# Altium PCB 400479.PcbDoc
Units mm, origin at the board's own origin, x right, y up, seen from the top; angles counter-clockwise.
Board outline 46.04 x 15.24 mm, 4 copper layers (Top Layer, Mid-Layer 1, Mid-Layer 2, Bottom Layer), stack 2.007 mm thick; 83 components, 46 nets, 247 pads, 135 vias.
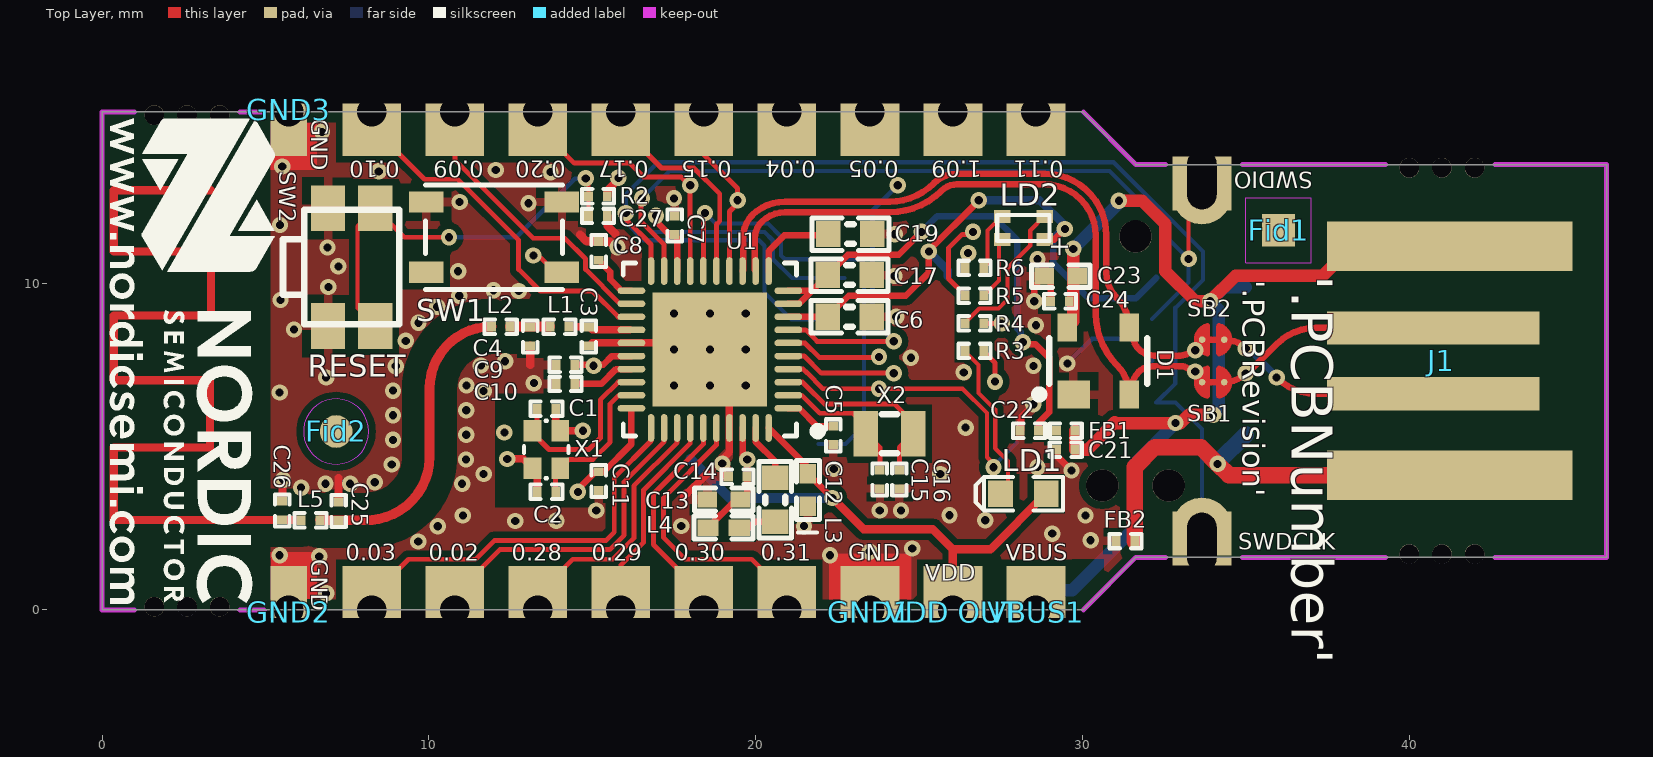
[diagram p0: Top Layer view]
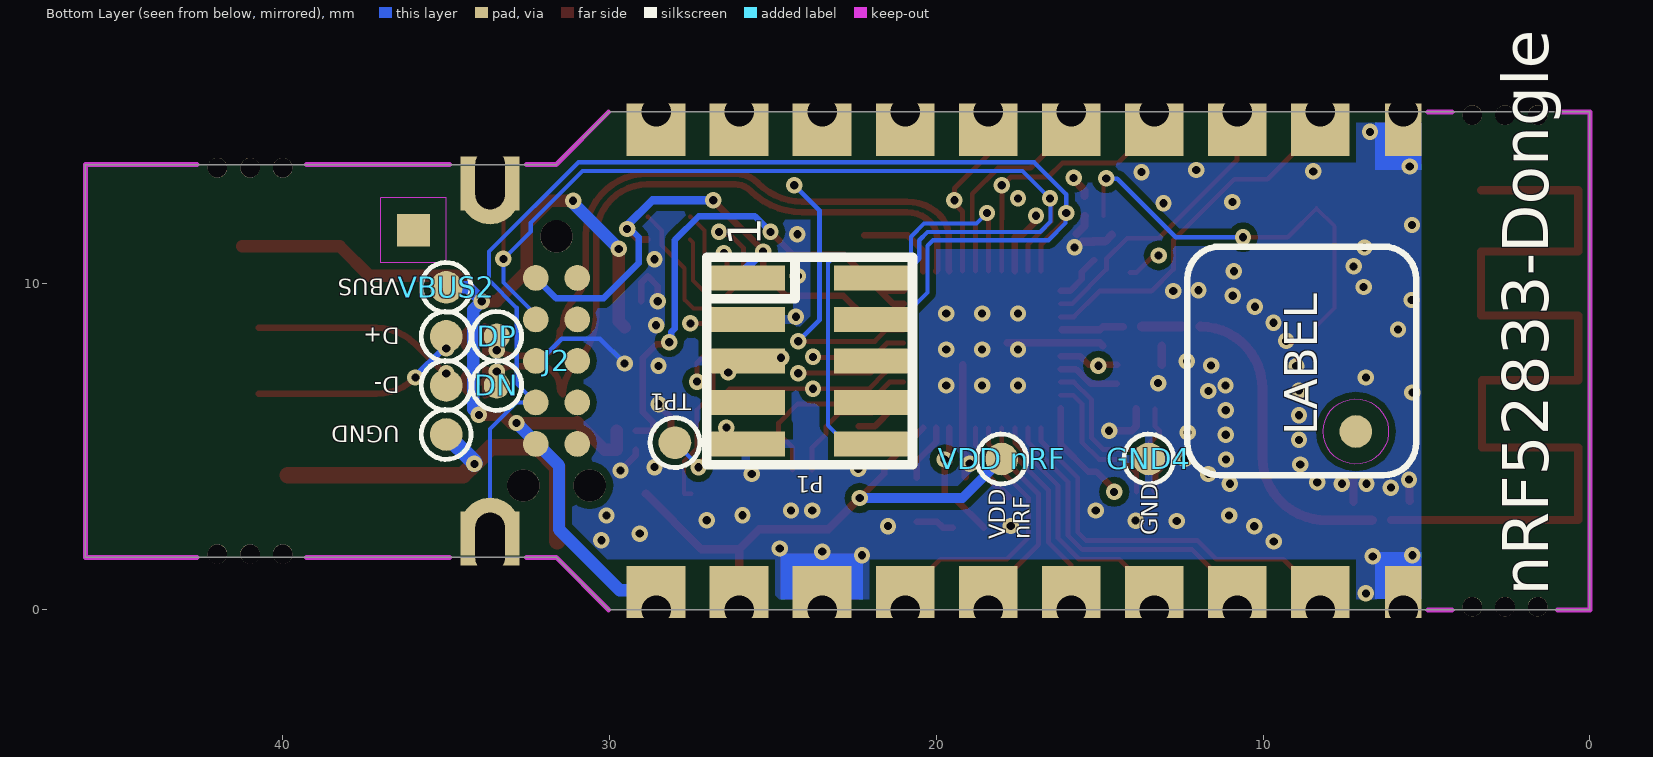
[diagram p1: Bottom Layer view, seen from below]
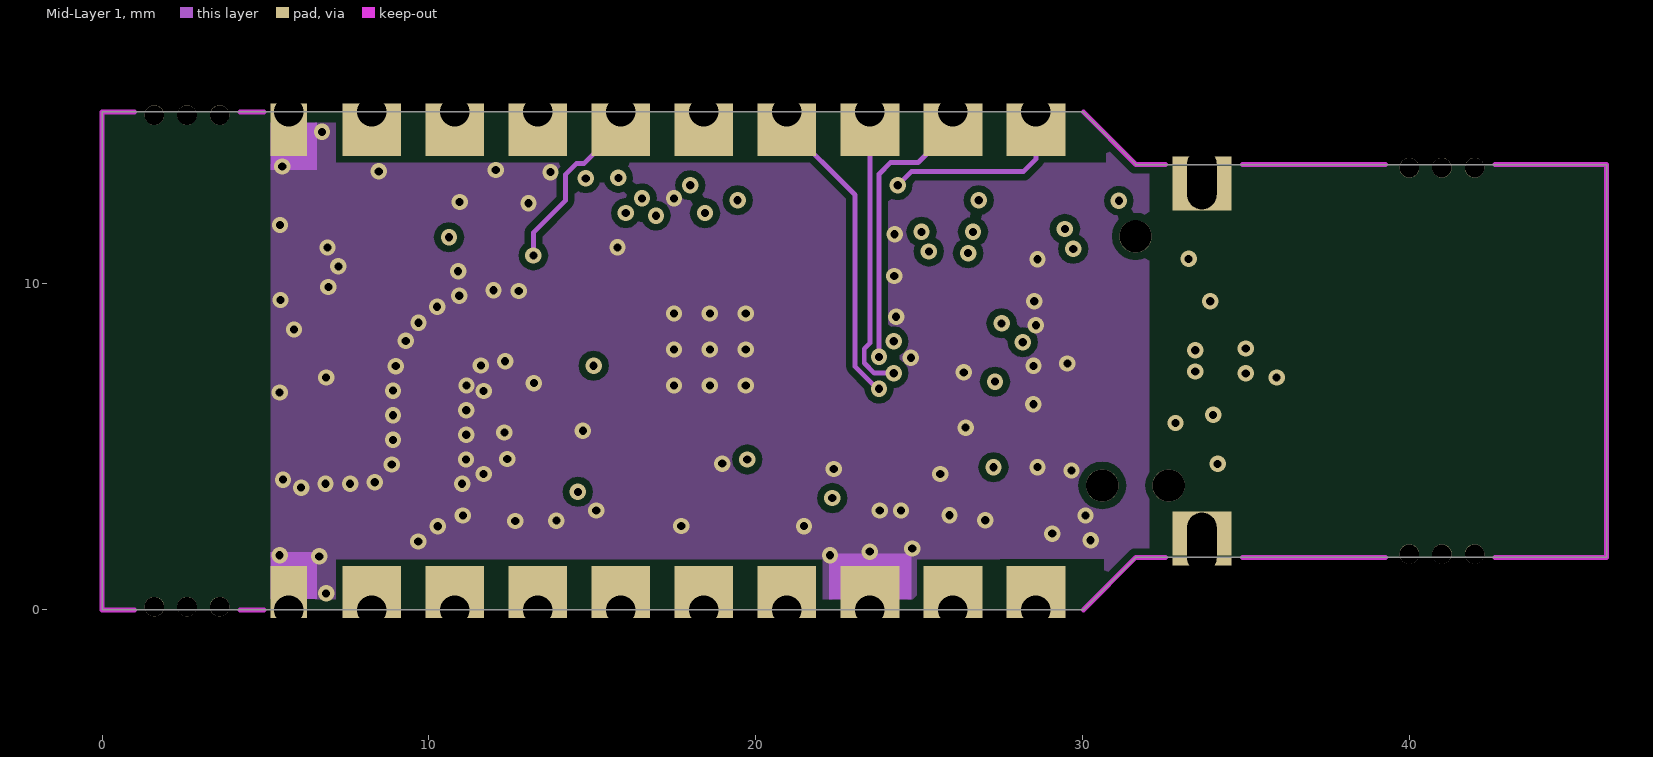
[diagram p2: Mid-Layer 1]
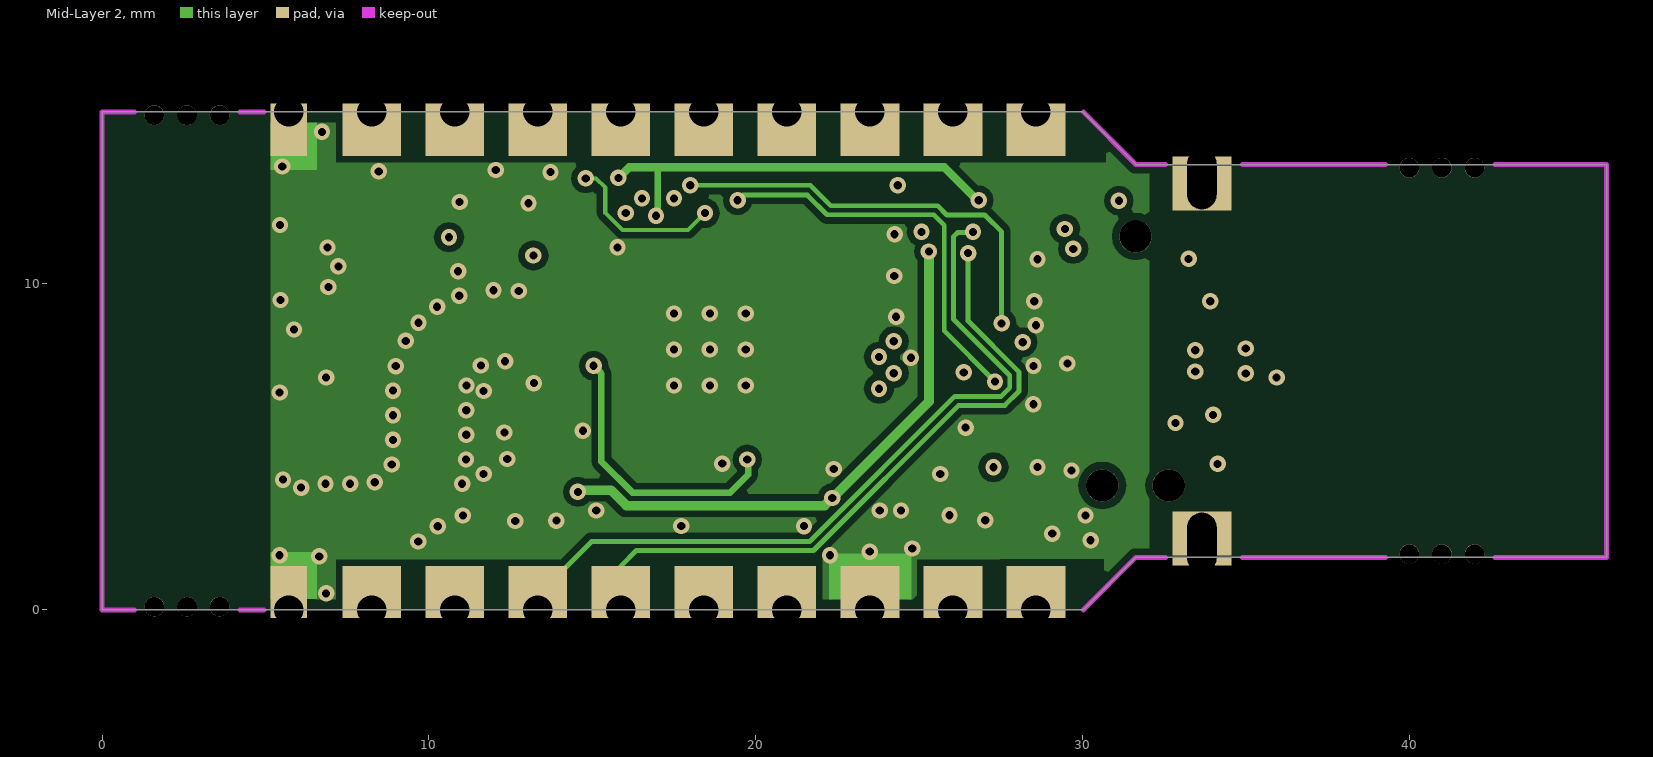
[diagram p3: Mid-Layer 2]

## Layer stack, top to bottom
Top Solder: solder mask 0.018, Solder Resist, Dk 3.5
Top Layer: signal copper 0.018
Dielectric1: prepreg 0.1, FR-4, Dk 4.1
Mid-Layer 1: signal copper 0.0356
Dielectric2: core 1.7, FR-4, Dk 4.5
Mid-Layer 2: signal copper 0.0356
Dielectric3: prepreg 0.1, FR-4, Dk 4.1
Bottom Layer: signal copper 0.018
Bottom Solder: solder mask 0.018, Solder Resist, Dk 3.5

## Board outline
0,0 0,15.24 30.027,15.24 31.637,13.63 46.039,13.63 46.039,1.61 31.637,1.61 30.027,0

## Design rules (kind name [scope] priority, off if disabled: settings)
Clearance ANT_Clerance [(InNet('ANT') or InNet('RF') or InNet('NetC4_2')) and (IsTrack or IsArc or IsVia) vs (InNamedPolygon('Top_Layer-GND')) or (InNamedPolygon('Bottom_Layer-GND')) or (InNamedPolygon('Mid_Layer_1-GND')) or (InNamedPolygon('Mid_Layer_2-GND'))] p1: gap=0.7 ignorepadtopadclearanceinfootprint=FALSE
Clearance NPTH [Not PadIsPlated And HoleSize > 0] p2: gap=0.229 ignorepadtopadclearanceinfootprint=FALSE except(0: Arc-Hole Track-Hole SMDPad-Hole THPad-Hole Via-Hole Fill-Hole Poly-Hole Region-Hole Text-Hole)
Clearance Polygon_Clearance [(InNamedPolygon('Top_Layer-GND')) or (InNamedPolygon('Bottom_Layer-GND')) or (InNamedPolygon('Mid_Layer_1-GND')) or (InNamedPolygon('Mid_Layer_2-GND'))] p3: gap=0.203 ignorepadtopadclearanceinfootprint=FALSE
Clearance SB_Clearance [HasFootprint('Solderbridge')] p4: gap=0.127 ignorepadtopadclearanceinfootprint=FALSE except(0: Arc-Hole Track-Hole SMDPad-Hole THPad-Hole Via-Hole Fill-Hole Poly-Hole Region-Hole Text-Hole)
Clearance [All] p5: gap=0.127 ignorepadtopadclearanceinfootprint=FALSE
ComponentClearance [All] p1 off: gap=0.254 collisioncheckmode=3 verticalgap=0.254 showdistances=FALSE
DiffPairsRouting [All] p1: maxlimit=2.54 minlimit=0.127 mostfreqgap=0.127 toplayer_maxgap=0.127 toplayer_minwidth=0.2 toplayer_maxwidth=0.2 toplayer_prefwidth=0.2 midlayer1_minwidth=0.381 midlayer1_maxwidth=0.381 midlayer1_prefwidth=0.381 midlayer2_minwidth=0.381 midlayer2_maxwidth=0.381 midlayer2_prefwidth=0.381 bottomlayer_maxgap=0.127 bottomlayer_minwidth=0.2 bottomlayer_maxwidth=0.2 bottomlayer_prefwidth=0.2 maxuncoupledlength=12.7
FabricationTestPointUsage TestPointUsage [All] p1: valid=0 allowmultiple=FALSE
FabricationTestpoint Testpoint [All] p1: side=3 testpointundercomponent=TRUE minsize=1.016 maxsize=2.54 preferedsize=1.524 minholesize=0 maxholesize=1.016 preferedholesize=0.813 testpointgrid=0.025 allowsidetop=TRUE allowsidebottom=TRUE usegrid=TRUE gridtolerance=0
Height [All] p1 off: minheight=0 maxheight=25.4 prefheight=12.7
HoleSize [All] p1: absolutevalues=TRUE maxlimit=2.54 minlimit=0.1 maxpercent=80.000 minpercent=20.000
MinimumAnnularRing [All] p1 off: minimumring=0.152
PolygonConnect PolygonConnect_1 [isVia and innet(gnd)] p1: connectstyle=Direct reliefconductorwidth=0.254 reliefentries=4 polygonreliefangle="90 Angle" airgapwidth=0.254
PolygonConnect [All] p2: connectstyle=Relief reliefconductorwidth=0.254 reliefentries=4 polygonreliefangle="90 Angle" airgapwidth=0.254
RoutingVias [All] p1: holewidth=0.25 width=0.5 viastyle="Through Hole" minholewidth=0.1 minwidth=0.3 maxholewidth=0.305 maxwidth=0.61
SilkToSolderMaskClearance SilkscreenOverComponentPads [IsPad] p1: minsilkscreentomaskgap=0.254 clearancetoexposedcopper=TRUE
SolderMaskExpansion [All] p1: expansion=0.076 istentingtop=FALSE
Width [All] p1: maxlimit=2.54 minlimit=0.127 preferedwidth=0.152 minimp=50.000000 maximp=50.000000 favimp=50.000000
23 further rules are at their usual default settings.

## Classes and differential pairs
differential pair D: +D_P -D_N

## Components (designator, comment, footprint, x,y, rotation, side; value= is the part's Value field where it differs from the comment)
0.02 "CH" Castellated_Hole_0.9mm 10.795,0 r0 top locked
0.03 "CH" Castellated_Hole_0.9mm 8.255,0 r0 top locked
0.04 "CH" Castellated_Hole_0.9mm 20.955,15.24 r180 top locked
0.05 "CH" Castellated_Hole_0.9mm 23.495,15.24 r180 top locked
0.09 "CH" Castellated_Hole_0.9mm 10.795,15.24 r180 top locked
0.10 "CH" Castellated_Hole_0.9mm 8.255,15.24 r180 top locked
0.11 "CH" Castellated_Hole_0.9mm 28.575,15.24 r180 top locked
0.15 "CH" Castellated_Hole_0.9mm 18.415,15.24 r180 top locked
0.17 "CH" Castellated_Hole_0.9mm 15.875,15.24 r180 top locked
0.20 "CH" Castellated_Hole_0.9mm 13.335,15.24 r180 top locked
0.28 "CH" Castellated_Hole_0.9mm 13.335,0 r0 top locked
0.29 "CH" Castellated_Hole_0.9mm 15.875,0 r0 top locked
0.30 "CH" Castellated_Hole_0.9mm 18.415,0 r0 top locked
0.31 "CH" Castellated_Hole_0.9mm 20.955,0 r0 top locked
1.09 "CH" Castellated_Hole_0.9mm 26.035,15.24 r180 top locked
C1 "12pF" CAPC0603X03L_C 13.596,6.154 r0 top
C2 "12pF" CAPC0603X03L_C 13.596,3.614 r180 top
C3 "1.0pF" CAPC0603X03L_C 14.9,8.37 r90 top
C4 "1.2pF" CAPC0603X03L_C 13.1,8.37 r90 top
C5 "100nF" CAPC0603X03L_C 22.375,5.345 r270 top
C6 "4.7µF" CAPC1608X06L 22.875,8.97 r0 top
C7 "100nF" CAPC0603X03L_C 17.525,11.77 r90 top
C8 "820pF" CAPC0603X03L_C 15.2,10.987 r90 top
C9 "N.C." CAPC0603X03L_C_NC 14.18,7.5 r0 top
C10 "100pF" CAPC0603X03L_C 14.18,6.916 r180 top
C11 "100nF" CAPC0603X03L_C 15.2,3.945 r270 top
C12 "1.0µF" CAPC1005X04L 21.6,3.67 r270 top
C13 "1.0µF" CAPC1005X04L 19.025,3.38 r0 top
C14 "47nF" CAPC0603X03L_C 19.451,4.08 r180 top
C15 "12pF" CAPC0603X03L_C 23.8,3.995 r270 top
C16 "12pF" CAPC0603X03L_C 24.4,3.995 r270 top
C17 "4.7µF" CAPC1608X06L 22.875,10.245 r0 top
C19 "4.7µF" CAPC1608X06L 22.9,11.5 r0 top
C21 "10nF" CAPC0603X03L_C 29.489,4.902 r0 top locked
C22 "100nF" CAPC0603X03L_C 28.372,5.486 r0 top locked
C23 "4.7µF" CAPC1005X04L 29.337,10.211 r0 top locked
C24 "100nF" CAPC0603X03L_C 29.312,9.449 r0 top locked
C25 "N.C." CAPC0603X03L_C_NC 7.239,3.023 r90 top locked
C26 "1.7pF" CAPC0603X03L_C 5.512,3.048 r270 top locked
C27 "100nF" CAPC0603X03L_C 15.173,12.057 r180 top
D1 "PRTR5V0U2X" SOT190P230X110-4L 30.48,7.62 r90 top locked
D+ "Ø1.0mm,SMD" TP_SMD_D1.0mm#1 35,8.37 r180 bottom locked
D- "Ø1.0mm,SMD" TP_SMD_D1.0mm#1 35,6.87 r180 bottom locked
DN "Ø1.0mm,SMD" TP_SMD_D1.0mm#2 33.45,6.87 r270 bottom locked
DP "Ø1.0mm,SMD" TP_SMD_D1.0mm#2 33.45,8.37 r270 bottom locked
FB1 "120R/0.85A" INDC0603X03L_C 29.489,5.486 r180 top locked
FB2 "120R/0.85A" INDC0603X03L_C 31.318,2.108 r180 top locked
Fid1 "Fiducial mark" Fiducial_Square 36,11.62 r0 top locked value=N.A.
Fid2 "Fiducial mark" Fiducial 7.163,5.461 r0 top locked value=N.A.
GND1 "GND" Castellated_Hole_0.9mm 23.495,0 r0 top locked
GND2 "GND" Castellated_Hole_0.9mm_S 5.715,0 r0 top locked
GND3 "GND" Castellated_Hole_0.9mm_S 5.715,15.24 r180 top locked
GND4 "GND" TP_SMD_D1.0mm#1 13.5,4.62 r180 bottom locked
J1 "USB-A" USB-A-PCB 41.039,7.63 r180 top locked
J2 "TC2050-IDC" TC2050-IDC-NLFP 31.623,7.62 r270 bottom locked
L1 "4.7nH" INDC0603X03L_C 14,8.67 r180 top
L2 "2.2nH" INDC0603X03L_C 12.2,8.67 r180 top
L3 "10µH" INDC1608X06L 20.6,3.37 r90 top
L4 "15nH" INDC1005X04L 19.021,2.52 r0 top
L5 "2.7nH" INDC0603X03L_C 6.375,2.743 r180 top locked
LD1 "L0603G" LED_0603_G 28.194,3.556 r0 top locked
LD2 "LED RGB" LED_RGB_0603 28.194,11.684 r90 top locked
P1 "Pin Header 2x5, 1.27mm" HDR_2x5-SMD-1.27mm-NC 23.876,7.62 r270 bottom locked
R2 "10k" RESC0603X03L_C 15.175,12.657 r0 top
R3 "220R" RESC0603X03L_C 26.695,7.925 r0 top locked
R4 "1k2" RESC0603X03L_C 26.695,8.771 r0 top locked
R5 "2k2" RESC0603X03L_C 26.695,9.618 r0 top locked
R6 "390R" RESC0603X03L_C 26.695,10.465 r0 top locked
SB1 "Solderbridge" Solderbridge_Shorted 34,6.97 r0 top locked net-tie
SB2 "Solderbridge" Solderbridge_Shorted 34,8.27 r0 top locked net-tie
SW1 "PB SW" C&K_PTS810 11.995,11.406 r180 top
SW2 "PTS840 GK SMTR LFS" EVQP7A_J_B_K 7.638,10.49 r270 top
SWDCLK "CH" Castellated_Hole_0.9mm_D 33.655,2.06 r0 top locked
SWDIO "CH" Castellated_Hole_0.9mm_D 33.655,13.18 r180 top locked
TP1 "Ø1.0mm,SMD" TP_SMD_D1.0mm#1 28,5.12 r180 bottom locked
U1 "nRF52833-QDAA" QFN40P500X500X50_HS-41N 18.6,7.97 r180 top locked
UGND "Ø1.0mm,SMD" TP_SMD_D1.0mm#1 35,5.37 r180 bottom locked
VBUS1 "VBUS" Castellated_Hole_0.9mm 28.575,0 r0 top locked
VBUS2 "VBUS" TP_SMD_D1.0mm#1 35,9.87 r180 bottom locked
"VDD nRF" "Ø1.0mm,SMD" TP_SMD_D1.0mm#1 18,4.62 r180 bottom locked
"VDD OUT" "CH" Castellated_Hole_0.9mm 26.035,0 r0 top locked
X1 "32MHz" BT-XTAL_1612 13.596,4.909 r270 top
X2 "32.768kHz" XTAL_2012 24.1,5.395 r0 top

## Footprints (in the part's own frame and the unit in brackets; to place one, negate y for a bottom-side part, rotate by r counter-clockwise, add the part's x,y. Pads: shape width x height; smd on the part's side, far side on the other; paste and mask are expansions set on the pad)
BT-XTAL_1612 [mm] "Crystal 1.6 x 1.2 mm"
  rect 0.65x0.55 smd: 1(-0.575,-0.425) 2(0.575,-0.425) 3(0.575,0.425) 4(-0.575,0.425)
  silkscreen extent -0.88,-0.68 0.88,0.68, body extent -0.83,-0.63 0.83,0.63, height 0.41
C&K_PTS810 [mm] "Microminiature SMT Top Actuated"
  rect 1.05x0.65 smd: 0(2.075,1.075) 1(-2.075,1.075) 2(-2.075,-1.075) 2(2.075,-1.075)
  silkscreen extent -2.1,-1.6 2.1,1.6, body extent -2.29,-1.6 2.29,1.6, height 2.5
CAPC0603X03L_C [mm] "Chip Capacitor, 2-Leads, Body 0.6x0.3mm, IPC High Density"
  rect 0.27x0.3 smd: 1(-0.285,0) 2(0.285,0)
  silkscreen extent -0.49,-0.22 0.49,0.22, body extent -0.3,-0.15 0.31,0.15, height 0.3
CAPC0603X03L_C_NC [mm] "Chip Capacitor, 2-Leads, Body 0.6x0.3mm, IPC High Density"
  rect 0.27x0.3 smd mask+0.05: 1(-0.285,0) 2(0.285,0)
  silkscreen extent -0.49,-0.22 0.49,0.22
CAPC1005X04L [mm] "Chip Capacitor, 2-Leads, Body 1.0x0.5mm, IPC High Density"
  rect 0.6x0.5 smd: 1(-0.5,0) 2(0.5,0)
  silkscreen extent -0.9,-0.35 0.9,0.35, body extent -0.51,-0.25 0.51,0.25, height 0.5
CAPC1608X06L [mm] "Chip Capacitor, 2-Leads, Body 1.6x0.8mm, IPC High Density"
  rect 0.75x0.8 smd: 1(-0.675,0) 2(0.675,0)
  silkscreen extent -1.17,-0.5 1.17,0.5, body extent -0.8,-0.43 0.8,0.43, height 0.8
Castellated_Hole_0.9mm [mm]
  rect 1.8x0.25 hole 0.25 square: 1(0,-0.126)
  rect 1.8x1.35 hole 0.9 copper offset 0,0.675: 1(0,0)
Castellated_Hole_0.9mm_D [mm]
  rect 1.8x0.25 hole 0.25 square: 1(0,-0.576)
  rect 1.8x1.35 hole 0.9 slot 1.83 at 90 deg copper offset 0,0.275: 1(0,0)
  round 1.8 smd paste-5: 1(0,0.48)
  round 1.8 smd far side paste-5: 1(0,0.48)
Castellated_Hole_0.9mm_S [mm]
  rect 1.118x0.25 hole 0.25 square: 1(0,-0.126)
  rect 1.118x1.35 hole 0.9 copper offset 0,0.675: 1(0,0)
EVQP7A_J_B_K [mm] "Subminiature Side Actuated Tact Switch for SMT"
  rect 1.4x1.05 smd: 1(-1.8,0.725) 1(1.8,0.725) 2(-1.8,-0.725) 2(1.8,-0.725)
  silkscreen extent -1.75,-2.1 1.75,1.45, body extent -2.35,-2.1 2.35,1.45, height 1.35
Fiducial [mm] "Fiducial Mark"
  round 1 smd paste-0.6 mask+0.5: 0(0,0)
  round 1 smd far side paste+0 mask+0.5: 0(0,0)
  Top Layer keep-out circle w0.01: c0,0 r1
  Bottom Layer keep-out circle w0.01: c0,0 r1
Fiducial_Square [mm] "Fiducial Mark"
  rect 1x1 smd paste-10 mask+0.5: 0(0,0)
  rect 1x1 smd far side paste-10 mask+0.5: 0(0,0)
  Top Layer keep-out lines w0.01: -1,-1 -1,1 1,1 1,-1 -1,-1
  Bottom Layer keep-out lines w0.01: -1,-1 1,-1 1,1 -1,1 -1,-1
HDR_2x5-SMD-1.27mm-NC [mm] "SMT MICRO HEADER, (1,27) .050\""
  rect 0.76x2.4 smd: 1(-2.54,-1.95) 2(-2.54,1.95) 3(-1.27,-1.95) 4(-1.27,1.95) 5(0,-1.95) 6(0,1.95) 7(1.27,-1.95) 8(1.27,1.95) 9(2.54,-1.95) 10(2.54,1.95)
  silkscreen extent -3.18,-3.15 3.18,3.15
INDC0603X03L_C [mm] "Chip Inductor, 2-Leads, Body 0.6x0.3mm, IPC High Density"
  rect 0.27x0.3 smd: 1(-0.285,0) 2(0.285,0)
  silkscreen extent -0.49,-0.22 0.49,0.22, body extent -0.31,-0.16 0.31,0.16, height 0.26
INDC1005X04L [mm] "Chip Inductor, 2-Leads, Body 1.0x0.5mm, IPC High Density"
  rect 0.65x0.5 smd: 1(-0.475,0) 2(0.475,0)
  silkscreen extent -0.9,-0.35 0.9,0.35, body extent -0.5,-0.3 0.5,0.3, height 0.5
INDC1608X06L [mm] "Chip Inductor, 2-Leads, Body 1.6x0.8mm, IPC High Density"
  rect 0.75x0.8 smd: 1(-0.675,0) 2(0.675,0)
  silkscreen extent -1.17,-0.5 1.17,0.5, body extent -0.8,-0.48 0.8,0.48, height 0.8
LED_0603_G [mil] "SMD Super Bright LED, GREEN"
  rect 30x32 smd: 1(-27.5,0) 2(27.5,0)
  silkscreen extent -58,-20 48,20, body extent -32,-16 32,16, height 24
LED_RGB_0603 [mm]
  rect 0.4x0.5 smd paste+0: 1(0.35,-0.65) 2(-0.35,0.65) 3(0.35,0.65) 4(-0.35,-0.65)
  silkscreen extent -0.4,-0.8 0.4,0.8, body extent -0.4,-0.8 0.4,0.8, height 0.5
QFN40P500X500X50_HS-41N [mm] "QFN, 40-Leads, Body 5.00x5.00mm, Pitch 0.40mm, Thermal Pad 3.60x3.60mm, IPC Medium Density"
  oval 0.85x0.2 smd: 1(-2.4,1.8) 2(-2.4,1.4) 3(-2.4,1) 4(-2.4,0.6) 5(-2.4,0.2) 6(-2.4,-0.2) 7(-2.4,-0.6) 8(-2.4,-1) 9(-2.4,-1.4) 10(-2.4,-1.8) 21(2.4,-1.8) 22(2.4,-1.4) 23(2.4,-1) 24(2.4,-0.6) 25(2.4,-0.2) 26(2.4,0.2) 27(2.4,0.6) 28(2.4,1) 29(2.4,1.4) 30(2.4,1.8)
  oval 0.2x0.85 smd: 11(-1.8,-2.4) 12(-1.4,-2.4) 13(-1,-2.4) 14(-0.6,-2.4) 15(-0.2,-2.4) 16(0.2,-2.4) 17(0.6,-2.4) 18(1,-2.4) 19(1.4,-2.4) 20(1.8,-2.4) 31(1.8,2.4) 32(1.4,2.4) 33(1,2.4) 34(0.6,2.4) 35(0.2,2.4) 36(-0.2,2.4) 37(-0.6,2.4) 38(-1,2.4) 39(-1.4,2.4) 40(-1.8,2.4)
  rect 3.5x3.5 smd: 41(0,0)
  silkscreen extent -3.43,-2.65 2.65,2.65, body extent -2.5,-2.5 2.5,2.5, height 0.5
RESC0603X03L_C [mm] "Chip Resistor, 2-Leads, Body 0.6x0.3mm, IPC High Density"
  rect 0.27x0.3 smd: 1(-0.285,0) 2(0.285,0)
  silkscreen extent -0.49,-0.22 0.49,0.22, body extent -0.3,-0.15 0.3,0.15, height 0.23
Solderbridge_Shorted [mm]
  round 0.2 smd paste-10: 1(-0.338,0) 2(0.338,0)
  Top Layer region: 0.102,0.432 0.178,0.505 0.296,0.467 0.361,0.424 0.434,0.351 0.488,0.292 0.546,0.193 0.574,0.099 0.569,-0.122 0.544,-0.193 0.46,-0.33 0.376,-0.411 0.284,-0.469 0.183,-0.5 0.132,-0.483 0.102,-0.43
  Top Layer region: -0.102,-0.432 -0.178,-0.505 -0.296,-0.467 -0.361,-0.424 -0.434,-0.351 -0.488,-0.292 -0.546,-0.193 -0.574,-0.099 -0.569,0.122 -0.544,0.193 -0.46,0.33 -0.376,0.411 -0.284,0.469 -0.183,0.5 -0.132,0.483 -0.102,0.43
  Top Layer lines w0.152: -0.178,-0.431 cw(c-0.068,0) -0.178,0.431 ; 0.178,-0.431 ccw(c0.068,0) 0.178,0.431
  Top Layer lines w0.203: -0.338,0 0.338,0
SOT190P230X110-4L [mm] "SOT143, 4-Leads, Body 3.0x2.5mm (max), Pitch 1.90mm, IPC High Density"
  rect 0.85x1 smd: 1(-1.025,0.75)
  rect 0.85x0.6 smd: 2(-1.025,-0.95) 3(1.025,-0.95) 4(1.025,0.95)
  silkscreen extent -1.15,-1.5 0.7,1.92, body extent -1.21,-1.46 1.21,1.46, height 1
TC2050-IDC-NLFP [mil]
  round 39 hole 39 unplated mask+3: 0(-150,0) 0(150,-40) 0(150,40)
  round 31 smd paste-196.85: 1(-100,-25) 2(-50,-25) 3(0,-25) 4(50,-25) 5(100,-25) 6(100,25) 7(50,25) 8(0,25) 9(-50,25) 10(-100,25)
  Top Layer pour cut-out: -100,25 -100,-25 100,-25 100,25
TP_SMD_D1.0mm#1 [mm] "Test point - pad 1.0mm"
  round 1 smd paste-5: 1(0,0)
  silkscreen extent -0.76,-0.76 0.76,0.76
TP_SMD_D1.0mm#2 [mm] "Test point - pad 1.0mm"
  round 0.8 smd paste-5: 1(0,0)
  silkscreen extent -0.76,-0.76 0.76,0.76
USB-A-PCB [mil]
  rect 296x60 smd paste-196.85: 1(-7.87,-137.8) 4(-7.87,138)
  rect 256x40 smd paste-196.85: 2(12,-39.37) 3(12,40)
XTAL_2012 [mm] "XTAL SMD 2.0 x 1.2 mm"
  rect 0.75x1.4 smd: 1(-0.725,0) 2(0.725,0)
  silkscreen extent -0.24,-0.6 0.24,0.6, body extent -1,-0.61 1,0.61, height 0.6

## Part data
0.02 0.03 0.04 0.05 0.09 0.10 0.11 0.15 0.17 0.20 0.28 0.29 0.30 0.31 1.09 GND1 VBUS1 "VDD OUT": library part "Castellated Hole 0.9mm", "Castellated Hole 0.9mm", Manufacturer=N.A.
C1 C2 C15 C16: library part C0201-12p, "Capacitor, NP0, ±2%", Manufacturer=N.A., Part number IPS=00000007848
C3: library part C0201-1.0p, "Capacitor, NP0, ±0.05pF, 50V", Manufacturer=N.A., Part number IPS=00000001247
C4: library part C0201-1.2p, "Capacitor, C0G, ±0.1pF, 50V", Manufacturer=N.A., Part number IPS=00000003190
C5 C7 C11 C22 C24 C27: library part C0201-100n, "Capacitor, X5R, ±10%", Manufacturer=N.A., Part number IPS="00000001248, 00000002505"
C6 C19: library part C0603-4µ7-6.3V-X7R, "Capacitor, X7R, ±10%, 6.3V", Manufacturer="Samsung Electro-Mechanics America", Manufacturer Part Number=CL10B475KQ8NQNC, Part number IPS=00000002541, Part number Norautron=N.A., Supplier Part Number 1=1276-2087-1-ND
C8: library part C0201-820p, "Capacitor, X7R, ±10%", Manufacturer=N.A., Part number IPS=00000001249
C9 C25: library part C0201-N.C., "Not mounted", Manufacturer=N.A.
C10: library part C0201-100p, "Capacitor, NP0, ±2%, 25V", Manufacturer=Murata, Manufacturer Part Number=GRM0335C1E101GA01, Part number IPS=00000007853, Part number Norautron=N.A.
C12 C13: library part C0402-1µ0, "Capacitor, X5R, ±5%, 6.3V", Manufacturer=N.A., Part number IPS="00000007786, 00000003457", Supplier Part Number 1=1276-1444-1-ND
C14: library part C0201-47n, "Capacitor, X5R, ±10%", Manufacturer=N.A., Part number IPS=00000001250
C17: library part C0603-4µ7-10V-X7S, "Capacitor, X7S, ±10%, 10V", Manufacturer=N.A., Part number IPS=00000001779, Supplier Part Number 1=445-14258-1-ND
C21: library part C0201-10n, "Capacitor, X7R, ±10%", Manufacturer=N.A., Part number IPS=00000003480
C23: library part C0402-4µ7, "Capacitor, X5R, ±20%", Manufacturer=N.A., Part number IPS="00000001251, 00000007165", Supplier Part Number 1=490-13252-1-ND
C26: library part C0201-1.7p, "Chip Cap 0201", Manufacturer=N.A.
D1: "Ultra low capacitance double rail-to-rail ESD protection diode", Manufacturer="NXP Semiconductors", Part number IPS=00000009951, Part number Norautron=N.A., Supplier Part Number 1=568-4140-1-ND
D+ D- DN DP GND4 TP1 UGND VBUS2 "VDD nRF": library part TP_SMD_Ø1.0MM, "1.0mm circular SMD testpad", Manufacturer="Nordic Semiconductor", Manufacturer Part Number=N.A.
FB1 FB2: library part FB0201-120R@100M-850mA, "Ferrite Bead, 120 Ohm @ 100MHz, 850mA, 150 mOhm Max", Manufacturer="Taiyo Yuden", Manufacturer Part Number=BKP0603HS121-T, Part number IPS=00000001252, Part number Norautron=N.A., Supplier Part Number 1=587-3286-1-ND
Fid1: library part Fid-Mark-Square, "Fiducial Mark", Manufacturer=N.A.
Fid2: library part Fid-Mark, "Fiducial Mark", Manufacturer=N.A.
GND2 GND3: library part "Castellated Hole 0.9mm_S", "Castellated Hole 0.9mm", Manufacturer=N.A.
J1: library part USB-A-PCB, "USB-A PCB footprint", Manufacturer=N.A.
J2: library part TC2050-IDC-NLFP, "CBL PLUG-OF-NAILS 10-PIN", Manufacturer="Tag-Connect LLC", Part number IPS=N.A., Supplier Part Number 1=TC2050-IDC-NL-ND
L1: library part L0201-4n7, "Inductor, 350mA, ±3%", Manufacturer=Murata, Manufacturer Part Number=LQP03TN4N7H02D, Part number IPS=00000001792, Part number Norautron=N.A.
L2: library part L0201-2n2, "Chip Inductor", Manufacturer=N.A.
L3: library part L0603-10µ-TDK, "Inductor, 250mA, ±20%, 1.05ohm. -55°C ~ 125°C", Manufacturer="TDK Corporation", Manufacturer Part Number=MLZ1608M100WTD25, Part number IPS=N.A., Supplier Part Number 1=445-175588-1-ND
L4: library part L0402-15n, "Inductor, 320mA, ±5%", Manufacturer="Taiyo Yuden", Manufacturer Part Number=HK100515NJ-T, Part number IPS=00000001262, Part number Norautron=N.A., Supplier Part Number 1=587-1521-1-ND
L5: library part L0201-2n7, "Chip Inductor", Manufacturer=N.A.
LD1: library part "VS 25C7M5", "LED, Green, 0603, 573nm, Vf=2.0V, 24mcd, - 40 to +85°C", Manufacturer="Victory Electronics", Part number IPS="00000001274, 00000009961", Part number Norautron=N.A.
LD2: library part APHF1608LSEEQBDZGKC, "RGB LED 1.60 mm x 0.80 mm SMD", Manufacturer="Kingbright Company LLC", Part number IPS=00000001254, Part number Norautron=N.A., Supplier Part Number 1=754-2143-1-ND
P1: library part "Pin Header 2x5 SMD, 1.27mm, KS, N.C.", "Pin Header 2x5, 1.27mm (50mil), SMD, Keying Shroud", Manufacturer=W-CON, Manufacturer Part Number=3132-10MS0BK00R1, Part number IPS=N.A.
R2: library part R0201-10k, "Resistor, ±1%, 0.05W", Manufacturer=N.A., Part number IPS=00000001255
R3: library part R0201-220, "Resistor, ±1%, 0.05W", Manufacturer=N.A., Part number IPS=00000000863
R4: library part R0201-1k2, "Resistor, ±1%, 0.05W", Manufacturer=N.A., Part number IPS=00000001256
R5: library part R0201-2k2, "Resistor, ±1%, 0.05W", Manufacturer=N.A., Part number IPS=00000001257
R6: library part R0201-390, "Resistor, ±1%, 0.05W", Manufacturer=N.A., Part number IPS=00000001258
SB1 SB2: library part "Solderbridge Shorted", "Shorted Solderbridge", Manufacturer=N.A.
SW1: library part "PTS810 SJK 250 SMTR LFS", "Tactile Switch, SPNO, SMD, 260gf, 4.2x3.2x2.5mm", Manufacturer=C&K, Part number IPS=00000001259, Part number Norautron=N.A., Supplier Part Number 1=CKN10503TR-ND
SW2: "Microminiature SMT Switch, Side Actuated", Manufacturer=C&K, Part number IPS=00000001260, Part number Norautron=N.A., Supplier Part Number 1=CKN10508CT-ND
SWDCLK SWDIO: library part "Castellated Hole 0.9mm_D", "Castellated Hole 0.9mm", Manufacturer=N.A.
U1: "Multi-protocol Bluetooth Low Energy, IEEE 802.15.4, ANT and 2.4GHz proprietary system-on-chip", Manufacturer="Nordic Semiconductor", Part number IPS=N.A.
X1: library part XTAL_SMD1612_32MHz_8pF_General, "XTAL SMD 1612, 32MHz, Cl=8pF, Total Tol: ±40ppm", Manufacturer=N.A.
X2: library part XTAL_SMD2012_32.768kHz_9pF_General, "XTAL SMD 2012, 32.768kHz, Cl=9pF, Total Tol: ±50ppm", Manufacturer=N.A.

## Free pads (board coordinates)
  round 1.8 smd paste-5: 3(33.655,2.54) 3(33.655,12.7)
  round 1.8 smd far side paste-5: 3(33.655,2.54) 3(33.655,12.7)
  round 0.6 hole 0.6 unplated paste+0 mask+0.102: 4(1.6,0.1) 4(1.6,15.14) 4(2.6,0.1) 4(2.6,15.14) 4(3.6,0.1) 4(3.6,15.14) 4(40,1.71) 4(40,13.53) 4(41,1.71) 4(41,13.53) 4(42,1.71) 4(42,13.53)

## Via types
v1: diameter 0.5, hole 0.25, Top Layer to Bottom Layer, tented both sides, 135 vias

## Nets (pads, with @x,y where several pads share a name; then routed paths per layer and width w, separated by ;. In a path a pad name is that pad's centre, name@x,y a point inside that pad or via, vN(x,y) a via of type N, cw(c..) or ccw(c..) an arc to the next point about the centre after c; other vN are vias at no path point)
ANT: C26.2 L5.2 | length 30.6
  Top Layer w0.254: 3.327,12.846 0.363,12.846 0.363,10.966 3.332,10.966 3.332,9.01 0.363,9.01 0.363,7.029 3.307,7.029 3.307,4.972 0.363,4.972 0.363,2.754 L5.2@6.09,2.754
D_N: D1.2 DN.1 SB1.1 U1.12 | length 21.1
  Top Layer w0.2: 19.975,11.401 19.975,11.376 ; U1.12 cw(c20.06,10.43) 19.975,10.43 19.975,11.376 ; SB1.1 33.3,7.332 ccw(c33,7.032) 33,7.457 32.15,7.457 ccw(c32.15,6.836) 31.53,6.836 cw(c31.189,6.836) D1.2 ccw(c30.163,6.595) 31.059,7.491 cw(c32.632,9.065) 30.407,9.065 30.407,11.456 ccw(c28.839,11.456) 28.839,13.023 26.162,13.023 ccw(c26.162,12.345) 25.682,12.825 cw(c24.096,14.41) 24.096,12.168 20.9,12.168 ccw(c20.9,11.149) 20.18,11.87 ccw(c20.674,11.376) 19.975,11.376
  other v1: 33.45,7.295
D_P: D1.3 DP.1 SB2.1 U1.13 | length 20
  Top Layer w0.2: U1.13 ccw(c19.537,10.433) 19.626,10.433 19.626,11.429 ; 19.626,11.454 19.626,11.429 ; SB2.1 33.3,7.908 cw(c33,8.208) 33,7.783 32.2,7.783 cw(c32.2,8.454) 31.53,8.454 ccw(c31.309,8.454) 31.465,8.61 D1.3 ccw(c30.163,8.645) 31.059,9.541 cw(c31.843,10.325) 30.734,10.325 30.734,11.456 ccw(c28.839,11.456) 28.839,13.35 26.162,13.35 ccw(c26.162,12.345) 25.451,13.056 cw(c24.096,14.41) 24.096,12.495 20.9,12.495 ccw(c20.9,11.074) 19.895,12.079 ccw(c20.546,11.429) 19.626,11.429
  other v1: 33.45,7.945
DEC1: C5.1 U1.1 | length 1.6
  Top Layer w0.2: U1.1 21.333,6.17 21.879,5.624 C5.1@22.375,5.624
DEC3: C10.1 U1.27 | length 1.9
  Top Layer w0.2: C10.1@14.485,6.917 15.279,6.917 15.732,7.37 U1.27
DEC4_6: C9.2 C13.2 C14.1 L4.1 U1.26 U1.38 | length 14
  Top Layer w0.2: C9.2 15.335,7.5 15.605,7.77 U1.26 ; L4.1 19.406,3.38 C13.2 ; U1.38 19.6,4.655 19.678,4.655 v1@19.736,4.597 ; C13.2@19.743,3.423 v1(19.743,4.604)
  Mid-Layer 2 w0.2: v1(15.044,7.472) 15.282,7.234 15.282,4.538 16.23,3.59 19.22,3.59 19.768,4.138 v1@19.768,4.554
GND: C1.2 C2.2 C3.1 C4.1 C5.2 C6.2 C7.2 C8.2 C9.1 C10.2 C11.2 C12.2 C13.1 C14.2 C15.2 C16.2 C17.2 C19.2 C21.1 C22.1 C23.1 C24.1 C25.2 C26.1 C27.1 D1.1 FB2.2 GND1.1 GND2.1 GND3.1 GND4.1 J2.3 P1.3 P1.5 P1.9 SW1.2 SW2.2 U1.25 U1.37 U1.41 X1.2 X1.4 | length 21.4
  Top Layer w0.203: C22.1 28.12,5.52 28.12,5.89 28.5,6.27 v1(28.5,6.295) ; v1(28.524,9.449) 28.524,9.906 28.829,10.211 C23.1 29.027,10.021 C24.1 ; C21.1 29.204,4.73 v1(29.667,4.267)
  Top Layer w0.229: v1(12.4,4.62) 12.885,4.62 X1.2 13.311,4.194 C2.2@13.311,3.665 ; C1.2 13.881,5.624 X1.4 v1(14.714,5.484) ; C3.1@14.909,8.085 14.994,8.17 U1.41@17.825,8.17 ; 17.806,3.461 18.518,4.173 ; v1@18.975,4.32 18.975,4.604 19.2,4.829 U1.41@19.2,7.5 ; v1@18.981,4.503 19.115,4.369 C14.2@19.115,4.08
  Top Layer w0.254: C26.1 5.516,3.333 5.524,3.341 5.524,3.975 v1(5.537,3.988) ; C25.2 7.239,4.039 ; 13.1,7.497 C4.1 ; 14.625,11.485 14.83,11.28 15.192,11.28 C8.2 ; C8.2@15.175,11.272 15.183,11.264 15.539,11.264 15.708,11.095 v1(15.775,11.095) ; C27.1 15.466,12.049 15.466,11.752 15.708,11.509
  Bottom Layer w0.145: v1(29.54,7.544) 30.293,8.297 31.464,8.297 J2.3@32.131,7.63
  other v1: 6.858,0.508 6.647,1.638 5.436,1.674 22.275,1.674 23.492,1.786 24.79,1.88 9.677,2.093 30.251,2.134 29.077,2.335 10.274,2.563 17.725,2.57 21.479,2.566 12.645,2.72 13.903,2.735 27.026,2.743 11.043,2.892 25.933,2.896 30.093,2.892 15.125,3.045 23.8,3.045 24.45,3.045 6.093,3.742 6.837,3.864 7.591,3.864 11.018,3.861 8.344,3.909 11.678,4.162 25.648,4.162 22.39,4.316 28.625,4.37 8.867,4.451 18.981,4.478 11.139,4.606 8.904,5.204 11.146,5.36 12.313,5.432 26.425,5.579 8.904,5.958 11.146,6.114 5.436,6.655 8.904,6.712 11.678,6.702 11.151,6.868 17.5,6.87 18.6,6.87 19.7,6.87 13.215,6.941 6.858,7.112 26.37,7.27 8.989,7.461 28.501,7.47 11.592,7.479 12.334,7.609 24.75,7.72 17.5,7.97 18.6,7.97 19.7,7.97 9.292,8.233 5.875,8.581 28.575,8.712 9.684,8.787 24.3,8.97 17.5,9.07 18.6,9.07 19.7,9.07 10.255,9.28 5.463,9.483 10.93,9.614 12.75,9.761 11.977,9.782 6.925,9.884 24.244,10.22 10.897,10.363 7.233,10.512 28.625,10.731 6.899,11.091 24.252,11.495 5.445,11.78 13.05,12.445 10.944,12.482 17.5,12.595 8.47,13.42 13.725,13.398 12.05,13.462 5.513,13.57 6.731,14.63
LED1: 0.15.1 R3.2 U1.14 | length 18.7
  Top Layer w0.15: 18.415,15.24 18.415,13.93 19.45,12.895 v1(19.45,12.536) 19.45,12.441 19.2,12.191 U1.14 ; R3.2 26.98,7.91 27.325,7.565 v1(27.325,6.988)
  Mid-Layer 2 w0.15: v1(19.45,12.536) 19.609,12.695 21.581,12.695 22.184,12.092 25.452,12.092 25.772,11.772 25.772,8.54 v1(27.325,6.988)
LED2_B: 0.29.1 R6.1 U1.34 | length 27.5
  Top Layer w0.15: 0.29.1@15.875,0 15.875,1.37 16.575,2.07 16.575,3.672 18,5.097 U1.34 ; v1@26.401,10.92 26.406,10.916 26.406,10.469 R6.1
  Mid-Layer 2 w0.15: 0.29.1@15.875,0 15.875,1.343 16.35,1.818 21.772,1.818 26.212,6.259 27.627,6.259 28.054,6.686 28.054,7.289 26.501,8.842 v1(26.501,10.92)
LED2_G: 0.28.1 R5.1 U1.33 | length 34.1
  Top Layer w0.15: 0.28.1@13.335,0 13.335,0.48 14.408,1.553 15.634,1.553 16.275,2.194 16.275,3.796 17.6,5.121 U1.33 ; R5.1 26.41,9.633 25.9,10.144 25.9,11.07 26.325,11.495 26.636,11.495 v1@26.65,11.509
  Mid-Layer 2 w0.15: 0.28.1@13.335,0 13.335,0.45 14.98,2.095 21.657,2.095 26.097,6.536 27.512,6.536 27.777,6.8 27.777,7.175 26.049,8.902 26.049,11.419 26.176,11.546 v1@26.627,11.546
  other v1: 26.651,11.57
LED2_R: 0.20.1 R4.2 U1.17 | length 21.9
  Top Layer w0.15: 13.335,15.24 13.335,14.79 14.453,13.672 16.148,13.672 16.573,13.247 17.723,13.247 17.998,12.972 17.998,11.958 18,11.956 U1.17 ; R4.2@26.981,8.771 v1@27.526,8.771
  Mid-Layer 2 w0.15: v1(17.998,12.995) 21.673,12.995 22.299,12.369 25.567,12.369 25.852,12.084 27.011,12.084 27.526,11.569 v1(27.526,8.77)
NetC3_2: C3.2 L1.1 U1.24 | length 1.9
  Top Layer w0.229: L1.1 14.894,8.67 14.909,8.655 14.994,8.57 U1.24@16.15,8.57
NetC4_2: C4.2 L1.2 L2.1 | length 1.2
  Top Layer w0.3: L2.1 L1.2
NetC8_1: C8.1 U1.21 | length 1.5
  Top Layer w0.2: C8.1@15.175,10.702 15.19,10.702 15.55,10.342 15.55,10.117 15.897,9.77 U1.21
NetC19_1: C19.1 U1.11 | length 2.6
  Top Layer w0.2: U1.11 20.4,10.983 20.882,11.465 ; 20.878,11.468 C19.1@22.21,11.468
NetD+_1: D+.1 J1.3 SB2.2 | length 7
  Top Layer w0.2: SB2.2 34.351,8.27 cw(c34.351,7.352) v1(35,8.001) ; v1(35.941,7.112) ccw(c37.144,8.315) 37.144,6.614 J1.3
  Bottom Layer w0.2: D+.1@35.077,8.001 35.966,7.112 v1@36.043,7.112
NetD-_1: D-.1 J1.2 SB1.2 | length 7
  Top Layer w0.2: SB1.2 34.351,6.97 ccw(c34.351,7.888) v1(35,7.239) ccw(c35,7.355) 35.082,7.273 35.941,8.132 cw(c37.144,6.929) 37.144,8.63 J1.2
NetFB2_1: FB2.1 J1.4 UGND.1 | length 12.4
  Top Layer w0.508: FB2.1 31.603,4.374 32.207,4.978 33.63,4.978 v1(34.138,4.47) 34.483,4.125 J1.4@39.853,4.125
  Bottom Layer w0.508: v1(34.138,4.47) 34.138,4.508 UGND.1
NetL3_1: L3.1 L4.2 | length 1.2
  Top Layer w0.2: L4.2 19.8,2.52 19.975,2.695 20.177,2.695 L3.1
NetL3_2: L3.2 U1.39 | length 1.8
  Top Layer w0.2: U1.39 20,5.15 20.6,4.55 L3.2
NetLD1_1: LD1.1 R3.1 | length 5.1
  Top Layer w0.127: R3.1 26.41,7.91 26.825,7.495 26.825,6.638 27.33,6.132 27.33,4.949 27.72,4.56 27.72,3.556 LD1.1
NetLD2_1: LD2.1 R4.1 | length 4.6
  Top Layer w0.127: R4.1 26.41,8.786 26.844,9.22 27.429,9.22 27.703,9.494 27.703,10.456 28.403,11.157 28.403,11.613 28.825,12.034 LD2.1
NetLD2_2: LD2.2 R5.2 | length 1.9
  Top Layer w0.127: R5.2 27.449,10.086 27.449,11.239 LD2.2
NetLD2_3: LD2.3 R6.2 | length 1.8
  Top Layer w0.127: R6.2 27.1,10.584 27.1,11.609 27.525,12.034 LD2.3
P0.00/XL1: C15.1 U1.2 X2.1 | length 4.3
  Top Layer w0.15: U1.2 21.41,6.57 21.962,6.018 22.975,6.018 ; 22.975,6.02 23.375,5.62 X2.1 23.8,4.97 C15.1
P0.01/XL2: C16.1 U1.3 X2.2 | length 6
  Top Layer w0.15: U1.3 21.433,6.97 21.55,6.853 21.552,6.853 22.1,6.305 24.239,6.305 24.825,5.718 X2.2 24.4,4.97 C16.1
P0.02/AIN0: 0.02.1 U1.32 | length 10.2
  Top Layer w0.15: 0.02.1@10.795,0 10.795,0.465 12.175,1.845 15.534,1.845 15.975,2.286 15.975,3.921 17.2,5.146 U1.32
P0.03/AIN1: 0.03.1 U1.31 | length 12.3
  Top Layer w0.15: 0.03.1@8.255,0 8.255,0.429 9.378,1.552 11.432,1.552 12.002,2.122 15.42,2.122 15.675,2.377 15.675,4.045 16.8,5.17 U1.31
P0.04/AIN2: 0.04.1 TP1.1 U1.4 | length 19.1
  Top Layer w0.127: v1(23.775,6.77) 26.334,6.77 27.076,6.027 27.076,4.674 27.28,4.47 v1(27.28,4.369)
  Top Layer w0.15: U1.4 21.457,7.37 21.557,7.27 21.559,7.27 22.059,6.77 v1(23.775,6.77)
  Mid-Layer 1 w0.15: 20.955,15.24 20.955,14.79 23.046,12.699 23.046,7.443 23.719,6.77 v1(23.775,6.77)
  Bottom Layer w0.127: v1(27.28,4.369) 27.28,4.4 TP1.1
P0.05/AIN3: 0.05.1 U1.5 | length 12.2
  Top Layer w0.15: U1.5 21.483,7.77 22.008,7.245 v1(24.225,7.245)
  Mid-Layer 1 w0.15: 23.495,15.24 23.495,8.165 23.323,7.993 23.323,7.557 23.635,7.245 v1(24.225,7.245)
P0.09: 0.09.1 U1.22 | length 8.9
  Top Layer w0.15: 10.795,15.24 10.795,13.774 13.193,11.376 14.161,11.376 14.797,10.739 14.797,10.421 15.848,9.37 U1.22
P0.10: 0.10.1 U1.23 | length 11.3
  Top Layer w0.15: 8.255,15.24 8.255,14.765 8.28,14.765 9.867,13.178 10.886,13.178 12.748,11.317 12.748,10.422 13.409,9.761 15,9.761 15.791,8.97 U1.23
P0.11: 0.11.1 U1.7 | length 14.7
  Top Layer w0.15: U1.7 21.532,8.57 21.882,8.22 v1(24.226,8.22)
  Mid-Layer 1 w0.15: v1(24.35,12.995) 24.766,13.411 28.191,13.411 28.575,13.795 28.575,15.24
  Bottom Layer w0.15: v1(24.226,8.22) 23.582,8.864 23.582,12.227 v1(24.35,12.995)
P0.30/AIN6: 0.30.1 U1.35 | length 6.8
  Top Layer w0.15: U1.35 18.4,5.073 16.875,3.548 16.875,1.995 18.415,0.455 0.30.1@18.415,0
P0.31/AIN7: 0.31.1 U1.36 | length 9
  Top Layer w0.15: U1.36 18.8,5.049 17.175,3.424 17.175,2.22 17.842,1.553 19.878,1.553 20.955,0.476 0.31.1@20.955,0
P1.09: 1.09.1 U1.6 | length 11.9
  Top Layer w0.15: U1.6 21.508,8.17 21.958,7.72 23.75,7.72 v1(23.775,7.745)
  Mid-Layer 1 w0.15: v1@23.774,7.745 23.774,13.337 24.125,13.688 24.968,13.688 26.035,14.755 26.035,15.24
RESET: C27.2 P1.10 R2.1 SW2.1 U1.16 | length 32
  Top Layer w0.127: SW2.1@8.363,8.69 7.816,9.237 7.816,11.743 8.363,12.29 9.249,11.405 v1(10.617,11.405) ; v1(14.801,13.207) 14.801,13.106 14.89,13.018 R2.1 14.889,12.655 14.889,12.058 C27.2
  Top Layer w0.15: U1.16 18.4,12.095 v1(18.45,12.145)
  Mid-Layer 2 w0.127: v1(14.801,13.207) 15.117,13.207 15.4,12.924 15.4,12.148 15.923,11.625 17.93,11.625 v1(18.45,12.145)
  Bottom Layer w0.127: v1(10.617,11.405) 12.674,11.405 14.465,13.196 14.79,13.196 v1(14.801,13.207) ; v1(18.45,12.145) 18.771,11.824 20.374,11.824 20.779,11.419 20.779,10.85 20.899,10.731 23.205,10.731 23.316,10.619 23.316,5.651 22.746,5.08 P1.10
RF: C25.1 L2.2 L5.1 | length 9.5
  Top Layer w0.3: L5.1 8.073,2.743 ccw(c8.073,4.695) 8.46,2.782 ccw(c8.073,4.695) 10.025,4.695 10.025,6.78 cw(c11.915,6.78) L2.2
SW1: 0.17.1 SW1.1 U1.15 | length 13.5
  Top Layer w0.15: v1(13.2,10.845) 13.267,10.778 13.423,10.778 13.87,10.331 SW1.1 ; 15.875,15.24 15.875,14.77 17.121,13.524 18.108,13.524 18.902,12.73 18.902,11.897 18.8,11.795 U1.15
  Mid-Layer 1 w0.15: v1(13.2,10.845) 13.2,11.545 14.177,12.522 14.177,13.32 14.516,13.659 14.744,13.659 15.875,14.79 15.875,15.24
SWDCLK: J2.4 P1.4 pad.3@33.655,2.54 SWDCLK.1 U1.20 | length 40.8
  Top Layer w0.15: v1@16.026,11.958 16.8,11.184 U1.20
  Bottom Layer w0.127: P1.4 21.094,8.89 20.275,9.709 20.275,10.636 20.271,10.64 20.271,11.145 20.102,11.314 16.572,11.314 16.05,11.836 16.05,12.121 v1(16.026,12.145) 16.026,12.719 17.007,13.7 30.954,13.7 33.689,10.964 33.689,10.092 32.842,9.246 32.842,6.934 J2.4 32.843,6.35 33.655,5.538 33.655,2.54 33.655,2.06 33.655,1.61
SWDIO: J2.2 P1.2 pad.3@33.655,12.7 SWDIO.1 U1.19 | length 34.6
  Top Layer w0.127: v1(33.249,10.744) 33.249,13.224 33.655,13.63
  Top Layer w0.15: v1(16.525,12.595) 16.498,12.568 16.498,11.878 17.2,11.176 U1.19
  Bottom Layer w0.127: v1@16.396,12.536 16.509,12.423 16.509,11.883 16.822,11.57 20.269,11.57 20.525,11.314 20.525,10.745 21.11,10.16 P1.2 P1.2@22.715,10.16 ; v1(16.525,12.595) 17.366,13.435 30.825,13.435 32.41,11.85 32.41,11.582 v1(33.249,10.744) 33.249,10.018 J2.2@32.131,8.9 ; SWDIO.1@33.655,13.259 33.655,13.63
VBUS: C17.1 C22.2 FB1.2 U1.9 U1.10 | length 16.2
  Top Layer w0.2: U1.9 21.325,9.37 21.725,9.77 ; U1.10 21.725,9.77 ; v1(25.076,11.57) 24.378,10.872 22.827,10.872 C17.1 21.725,9.77 ; v1(28.175,8.194) 28.232,8.137 28.559,8.137 28.98,7.716 28.98,6.053 28.657,5.73 C22.2 ; C22.2 FB1.2
  Bottom Layer w0.2: v1(25.076,11.57) 25.553,12.047 27.273,12.047 28.003,11.317 28.003,8.609 28.118,8.495 28.118,8.251 v1(28.175,8.194)
VBUS': C21.2 C23.2 C24.2 D1.4 FB1.1 J1.1 J2.5 VBUS1.1 VBUS2.1 | length 35.5
  Top Layer w0.381: D1.4 29.718,8.833 v1(29.718,11.049) ; FB1.1 C21.2 30.15,4.902 30.988,5.74 31.008,5.72 v1(32.85,5.72) 33,5.72 33.25,5.97 v1(34,5.97) ; v1(31.115,12.522) 31.824,12.522 32.537,11.809 32.537,10.363 33.452,9.449 v1(33.909,9.449) 34.684,10.223 37.351,10.223 38.257,11.13 J1.1
  Bottom Layer w0.381: VBUS1.1@28.575,0 29.185,0.61 29.693,0.61 31.547,2.464 31.547,4.417 v1(32.85,5.72) ; v1(29.718,11.049) 31.115,12.446 v1(31.115,12.522) ; v1(34,5.97) 34.175,6.145 34.175,9.183 v1(33.909,9.449) 34.33,9.87 VBUS2.1
VDD_nRF: "VDD nRF.1" "VDD OUT.1" C6.1 C7.1 C11.1 C12.1 J2.1 LD1.2 LD2.4 P1.1 R2.2 U1.8 U1.18 U1.30 U1.40 | length 70.6
  Top Layer w0.2: v1@14.536,3.665 15.101,4.23 C11.1 15.355,4.23 16.2,5.075 U1.30 ; v1@16.87,11.975 17.36,11.485 C7.1 17.6,11.41 U1.18 ; U1.40 21.6,4.37 C12.1 v1(22.346,3.424) ; U1.8 C6.1 22.848,9.618 24.595,9.618 25.301,10.324 v1(25.301,10.97) ; v1@25.372,11.073 v1@26.695,12.395
  Top Layer w0.203: LD2.4 29.139,11.334 v1(29.464,11.659)
  Top Layer w0.25: R2.2@15.47,12.667 15.47,12.84 v1@15.826,13.196
  Top Layer w0.254: v1(22.346,3.424) 23.3,2.47 25.419,2.47 26.035,1.854 ; 26.035,0.178 26.035,1.854 ; LD1.2@28.889,3.559 27.184,1.854 26.035,1.854
  Mid-Layer 2 w0.2: v1(16.95,12.065) 17.009,12.124 17.009,13.545
  Mid-Layer 2 w0.25: v1(15.801,13.22) 16.125,13.545 17.009,13.545 25.775,13.545 v1@26.826,12.494
  Mid-Layer 2 w0.3: v1@14.536,3.665 15.57,3.665 16.045,3.19 22.113,3.19 v1(22.346,3.424) 25.301,6.379 25.301,10.895 v1@25.376,10.97
  Bottom Layer w0.203: v1@29.464,11.76 29.108,11.405 29.108,10.617 30.188,9.538 31.636,9.538 J2.1
  Bottom Layer w0.25: v1(26.826,12.536) 28.688,12.536 v1@29.464,11.76
  Bottom Layer w0.254: v1@25.368,10.962 25.368,10.902 25.875,10.395 P1.1@25.875,10.209
  Bottom Layer w0.3: 18,4.62 19.196,3.424 v1(22.346,3.424)
  other v1: 14.561,3.614
XC1: C1.1 U1.28 X1.1 | length 5.6
  Top Layer w0.15: C1.1 13.311,5.624 X1.1 13.171,5.416 13.678,4.909 14.897,4.909 15.25,5.262 15.25,6.429 15.791,6.97 U1.28
XC2: C2.1 U1.29 X1.3 | length 4.6
  Top Layer w0.15: C2.1 13.881,4.194 X1.3 14.296,4.609 15.022,4.609 15.55,5.137 15.55,6.305 15.815,6.57 U1.29
pads on no net: Fid1.0 Fid2.0 J2.0 J2.6 J2.7 J2.8 J2.9 J2.10 P1.6 P1.7 P1.8 SW1.0

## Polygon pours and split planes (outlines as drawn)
GND on Bottom Layer "Bottom_Layer-GND" (solid, remove dead copper, pour order 42): -2.54,-2.54 -2.54,17.78 48.26,17.78 48.26,-2.54
GND on Mid-Layer 2 "Mid_Layer_2-GND" (solid, remove dead copper, pour order 41): 0,0 0,15.24 30.027,15.24 31.637,13.63 46.039,13.63 46.039,1.61 31.637,1.61 30.027,0
GND on Mid-Layer 1 "Mid_Layer_1-GND" (solid, pour order 39): 0,0 0,15.24 30.027,15.24 31.637,13.63 46.039,13.63 46.039,1.61 31.637,1.61 30.027,0
GND on Top Layer "Top_Layer-GND" (solid, remove dead copper, pour order 37): -2.54,-2.606 -2.54,17.78 48.26,17.78 48.26,-2.606

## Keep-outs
Keep-Out Layer:
  lines w0.15: 30.027,0 31.637,1.61 32.537,1.61 ; 30.027,15.24 31.637,13.63 32.537,13.63 ; 34.9,1.61 39.27,1.61 ; 34.9,13.63 39.27,13.63 ; 42.628,1.61 46.039,1.61 46.039,13.63 42.628,13.63
  lines w0.152: 0.99,0 0,0 0,15.24 0.99,15.24 ; 4.216,0 4.953,0 ; 4.216,15.24 4.953,15.24

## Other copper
Top Layer:
  rectangle net GND: 22.25,0.326 24.765,1.727
  rectangle net GND: 5.156,0.33 6.579,1.778
  rectangle net GND: 5.156,13.462 6.579,14.91
  pour cut-out: 26.072,9.265 26.072,7.91 26.104,7.91 26.125,7.889 26.125,9.27
  pour cut-out: 22.225,5.187 22.225,4.933 22.2,4.933 22.2,5.187
  pour cut-out: 9.091,9.593 9.091,9.702 9.192,9.803 9.192,9.906 9.188,9.906 8.875,9.593
  pour cut-out: 4.693,14.91 4.693,15.606 31.394,15.606 31.394,14.91
  pour cut-out: 30.44,0.326 30.44,-2.605 4.483,-2.606 4.483,0.326
  pour cut-out: -0.508,16.724 5.156,16.724 5.156,-1.107 -0.508,-1.107
  pour cut-out: 12.021,6.636 12.021,3.131 15.037,3.131 15.037,6.636
  pour cut-out: 15.1,7.779 13.425,7.779 13.425,8.245 13.325,8.245 13.325,9.295 15.1,9.295
Mid-Layer 1:
  rectangle net GND: 5.156,13.462 6.579,14.91
  rectangle net GND: 5.156,0.33 6.579,1.778
  rectangle net GND: 22.25,0.326 24.765,1.727
  pour cut-out: 4.693,14.91 4.693,15.606 31.394,15.606 31.394,14.91
  pour cut-out: 30.44,0.326 30.44,-2.605 4.483,-2.606 4.483,0.326
  pour cut-out: -0.508,16.724 5.156,16.724 5.156,-1.107 -0.508,-1.107
Mid-Layer 2:
  rectangle net GND: 5.156,13.462 6.579,14.91
  rectangle net GND: 5.156,0.33 6.579,1.778
  rectangle net GND: 22.25,0.326 24.765,1.727
  pour cut-out: 4.693,14.91 4.693,15.606 31.394,15.606 31.394,14.91
  pour cut-out: 30.44,0.326 30.44,-2.605 4.483,-2.606 4.483,0.326
  pour cut-out: -0.508,16.724 5.156,16.724 5.156,-1.107 -0.508,-1.107
Bottom Layer:
  rectangle net GND: 22.25,0.326 24.765,1.727
  rectangle net GND: 5.156,0.33 6.579,1.778
  rectangle net GND: 5.156,13.462 6.579,14.91
  pour cut-out: 27.28,9.017 27.704,9.017 27.707,9.02 27.7,9.027 27.7,9.12 27.28,9.12
  pour cut-out: 23.85,11.945 23.85,12 23.855,11.995 24.947,11.995 24.947,11.945
  pour cut-out: 30.44,0.326 30.44,-2.605 4.223,-2.606 4.223,0.326
  pour cut-out: 4.743,14.91 4.743,15.606 31.394,15.606 31.394,14.91
  pour cut-out: -0.508,16.724 5.156,16.724 5.156,-1.107 -0.508,-1.107
Multi-Layer:
  pour cut-out: 32.039,1.61 32.039,13.63 46.039,13.63 46.039,1.61
  pour cut-out: 24.932,1.553 30.675,1.553 30.675,0.326 24.932,0.326
  pour cut-out: 30.725,13.687 7.152,13.687 7.152,14.914 30.725,14.914
  pour cut-out: 7.152,1.553 22.058,1.553 22.058,0.326 7.152,0.326

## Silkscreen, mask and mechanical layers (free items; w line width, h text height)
Top Overlay:
  drawing of 44 lines, arcs and shapes, not listed
  text "'.PCBNumber'" at 35.992,10.236 h2.16 r270
  text "'.PCBRevision'" at 34.9,10.084 h0.69 r270
  text "RESET" at 6.293,7.142 h0.69
  text "VDD" at 25.191,0.901 h0.51
Bottom Overlay:
  lines w0.2: 5.319,5.12 ccw(c6.319,5.12) 6.319,4.12 11.319,4.12 ccw(c11.319,5.12) 12.319,5.12 12.319,10.12 ccw(c11.319,10.12) 11.319,11.12 6.319,11.12 ccw(c6.319,10.12) 5.319,10.12 5.319,5.12
  text "LABEL" at 8.342,5.339 h1.02 r270
  text "VDD / nRF" at 17.137,2.165 h0.51 r270
  text "nRF52833-Dongle" at 0.813,0.432 h2.41 r270
Board Outline:
  the board outline again, w0.152
Bottom Assembly:
  drawing of 40 lines, arcs and shapes, not listed
Top Impedance Info:
  lines w0.229: 14.285,8.67 14.894,8.67 14.909,8.655 14.994,8.57 16.15,8.57
  lines w0.254: 5.3,2.754 6.09,2.754
  lines w0.3: 6.66,2.743 8.073,2.743 ccw(c8.073,4.695) 8.46,2.782 ccw(c8.073,4.695) 10.025,4.695 10.025,6.78 cw(c11.915,6.78) 11.915,8.67 ; 12.485,8.67 13.715,8.67
  text "50ohm impedance" at 4.525,10.195 h1.52
Placement:
  lines w0.152: 32.039,1.61 32.039,13.63

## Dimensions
31.637,1.61 to 46.039,1.61 on Dimension
0,0 to 46.039,1.61 on Dimension
0,0 to 30.027,0 on Dimension
46.039,13.63 to 46.039,1.61 on Dimension
0,15.24 to 0,0 on Dimension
